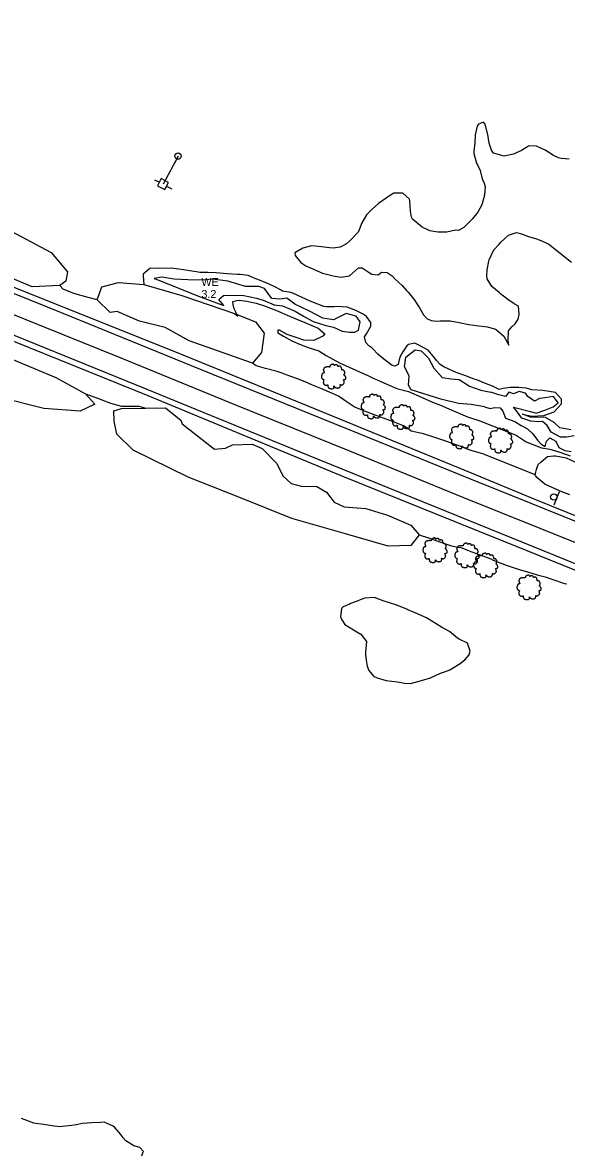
# Model space of a CAD drawing. Extents: x 2160437 to 2172832, y 205694 to 212444.
# Drawn here: x 2166438 to 2166778, y 208658 to 209361 of the extents above; entities that cross this region are included whole.
import ezdxf

# ---------------------------------------------------------------- set-up
doc = ezdxf.new("R2010")
doc.units = 0
for name, color, linetype in [('RD_EX_BldgApp', 7, 'Continuous'), ('RD_EX_H2O_Pond', 7, 'Continuous'), ('RD_EX_H2O_txCode', 7, 'Continuous'), ('RD_EX_LaneStripe', 7, 'Continuous'), ('RD_EX_Road', 7, 'Continuous'), ('RD_EX_UT', 7, 'Continuous'), ('RD_EX_UT_Guy', 7, 'Continuous'), ('RD_EX_VEG', 7, 'Continuous'), ('RD_EX_VEG_ShrubLine', 7, 'Continuous'), ('RD_EX_VEG_TreeLine', 7, 'Continuous')]:
    doc.layers.add(name, color=color, linetype=linetype)

# ---------------------------------------------------------------- blocks, each defined once
blk = doc.blocks.new('T2')
at = {"layer": 'RD_EX_VEG'}
for points in [[(0.05, 7.21), (-0.25, 7.24), (-0.57, 7.14), (-0.82, 7.04), (-1.05, 6.96), (-1.27, 6.86), (-1.57, 6.69), (-1.8, 6.49), (-1.92, 6.24), (-1.97, 6.01), (-2.02, 5.74), (-2.02, 5.56), (-2.15, 5.54), (-2.3, 5.56), (-2.55, 5.64), (-2.8, 5.64), (-3.05, 5.64), (-3.4, 5.61), (-3.75, 5.61), (-4.02, 5.56), (-4.35, 5.51), (-4.72, 5.39), (-5.07, 5.26), (-5.37, 5.01), (-5.62, 4.54), (-5.75, 4.19), (-5.9, 3.94), (-5.75, 3.49), (-5.57, 3.14), (-5.55, 2.94), (-5.47, 2.52), (-5.37, 2.29), (-5.25, 2.09), (-5.32, 2.07), (-5.7, 2.02), (-6, 1.92), (-6.42, 1.69), (-6.64, 1.47), (-6.74, 1.14), (-6.77, 0.79), (-6.87, 0.59), (-6.94, 0.32), (-6.97, 0.24), (-7.02, -0.08), (-6.92, -0.53), (-6.89, -0.88), (-6.77, -1.11), (-6.62, -1.28), (-6.44, -1.53), (-6.05, -1.76), (-5.72, -1.86), (-5.52, -1.88), (-5.7, -2.38), (-5.75, -2.73), (-5.87, -3.13), (-5.87, -3.21), (-5.92, -3.68), (-5.77, -4.01), (-5.7, -4.38), (-5.52, -4.61), (-5.25, -4.91), (-4.92, -5.13), (-4.42, -5.26), (-4.02, -5.23), (-3.45, -5.06), (-3.2, -4.98), (-3.22, -5.16), (-3.2, -5.53), (-3.2, -5.96), (-3.05, -6.28), (-2.95, -6.56), (-2.8, -6.81), (-2.47, -7.03), (-2.07, -7.11), (-1.65, -7.26), (-1.2, -7.33), (-0.7, -7.36), (-0.1, -7.21), (0.18, -7.08), (0.28, -6.91), (0.48, -6.53), (0.43, -6.31), (0.45, -5.71), (0.55, -5.88), (0.73, -6.23), (1.23, -6.53), (1.63, -6.71), (2.1, -6.86), (2.4, -6.93), (2.88, -6.86), (3.25, -6.78), (3.63, -6.66), (3.93, -6.38), (4.1, -6.11), (4.15, -5.83), (4.23, -5.46), (4.28, -5.28)], [(4.28, -5.28), (4.2, -5.11), (4.15, -4.86), (4.23, -4.88), (4.4, -4.93), (4.68, -5.06), (4.9, -5.13), (5.23, -5.11), (5.5, -5.01), (5.95, -4.73), (6.22, -4.26), (6.5, -3.86), (6.57, -3.53), (6.52, -3.31), (6.5, -2.81), (6.3, -2.56), (6.25, -2.43), (6.15, -2.03), (6.22, -1.98), (6.5, -1.93), (6.87, -1.81), (7.15, -1.68), (7.37, -1.51), (7.45, -1.28), (7.42, -0.88), (7.47, -0.48), (7.4, -0.33), (7.3, -0.18), (7.22, 0.02), (7.07, 0.17), (6.97, 0.32), (6.87, 0.42), (6.75, 0.57), (6.57, 0.69), (6.42, 0.74), (6.37, 0.89), (6.52, 1.09), (6.57, 1.19), (6.6, 1.42), (6.82, 1.77), (6.87, 2.17), (6.82, 2.59), (6.77, 2.87), (6.62, 3.14), (6.42, 3.39), (6.3, 3.56), (6.12, 3.69), (5.8, 3.81), (5.55, 3.86), (5.2, 3.86), (5, 3.91), (5.03, 3.96), (5.03, 4.11), (5.03, 4.39), (4.95, 4.84), (4.8, 5.34), (4.8, 5.36), (4.7, 5.61), (4.48, 5.81), (4.3, 5.91), (4.1, 6.04), (3.85, 6.06), (3.55, 6.06), (3.28, 6.01), (3.08, 5.91), (2.9, 5.79), (2.83, 5.94), (2.73, 6.24), (2.68, 6.39), (2.53, 6.56), (2.3, 6.76), (1.85, 6.89), (1.23, 6.81), (0.93, 6.61), (0.78, 6.44), (0.73, 6.56), (0.53, 6.76), (0.43, 6.94), (0.25, 7.06), (0.1, 7.16), (0, 7.21)]]:
    blk.add_spline(points, degree=3, dxfattribs=at)
blk = doc.blocks.new('PP')
at = {"layer": 'RD_EX_UT'}
for p, q in [((2.49, 2.51), (-2.51, 2.51)), ((-2.51, 2.51), (-2.51, -2.49)), ((2.49, -2.49), (2.49, 2.51)), ((-5.94, -0.05), (-2.47, -0.05)), ((-2.51, -2.49), (2.49, -2.49)), ((2.42, -0.05), (6.06, -0.05))]:
    blk.add_line(p, q, dxfattribs=at)

msp = doc.modelspace()

# ---------------------------------------------------------------- linework, layer by layer
at = {"layer": 'RD_EX_BldgApp'}
msp.add_line((2166770.22, 209059.45), (2166773.47, 209067.85), dxfattribs=at)
msp.add_circle((2166769.97, 209064.4), 2, dxfattribs=at)
at = {"layer": 'RD_EX_H2O_Pond'}
msp.add_lwpolyline([(2166647.86, 209168.59), (2166649.04, 209173.76), (2166646.54, 209177.41), (2166640.2, 209178.95), (2166636.96, 209177.34), (2166632.2, 209175.04), (2166625.66, 209176), (2166616.89, 209180.68), (2166608.09, 209184.88), (2166603.19, 209188.53), (2166598.68, 209187.98), (2166593.83, 209188.42), (2166589.09, 209194.58), (2166585.54, 209195.76), (2166577.32, 209195.92), (2166566.35, 209199.18), (2166556.72, 209200.45), (2166552.2, 209200.02), (2166545.52, 209199.73), (2166532.74, 209200.44), (2166524.94, 209201.67), (2166520.32, 209200.75), (2166523.06, 209199.88), (2166547.93, 209189.75), (2166560.8, 209184.98), (2166563.83, 209183.97), (2166560.71, 209187.72), (2166563.56, 209190.16), (2166568.4, 209190.5), (2166576.3, 209190.31), (2166584.19, 209188.62), (2166588.31, 209187.24), (2166595.17, 209184.33), (2166600.44, 209183.76), (2166608.32, 209180.45), (2166613.52, 209177.33), (2166619.51, 209174.09), (2166627.44, 209171.54), (2166632.33, 209170.54), (2166637.81, 209167.89), (2166642.27, 209167.26), (2166645.65, 209167.3)], close=True, dxfattribs=at)
for points in [[(2166726.72, 209120.69), (2166718.4, 209122.1), (2166710.33, 209122.85), (2166699.34, 209125.52), (2166680.77, 209131.24), (2166679.25, 209134.14), (2166679.67, 209140.14), (2166676.75, 209145.78), (2166677.59, 209151.65), (2166683.31, 209156.35), (2166687.16, 209155.69), (2166691.74, 209151.05), (2166694.98, 209144.78), (2166700.16, 209139.08), (2166705.89, 209138.19), (2166710.73, 209137.75), (2166717.23, 209133.62), (2166724.47, 209131.02), (2166730.54, 209129.84)], [(2166782.67, 209102.57), (2166777.82, 209101.78), (2166774.14, 209101.77), (2166768.26, 209104.88), (2166765.88, 209108.95), (2166762.98, 209111.64), (2166760.38, 209111.39), (2166755.6, 209111.69), (2166749.89, 209113.53), (2166746.59, 209118.21), (2166744.83, 209120.5), (2166755.44, 209117.8), (2166758.93, 209116.84), (2166764.27, 209118.59), (2166769.57, 209120.79), (2166772.61, 209123.22), (2166769.69, 209127.09), (2166764.42, 209126.31), (2166761.01, 209125.8), (2166757.92, 209124.22), (2166753.72, 209127.18), (2166752.22, 209129.24), (2166748.4, 209130.28), (2166744.72, 209128.9), (2166741.94, 209129.92), (2166739.71, 209127.19), (2166735.63, 209128.24), (2166730.54, 209129.84)], [(2166726.72, 209120.69), (2166730.19, 209119.68), (2166732.98, 209120.34), (2166736.49, 209120.12), (2166738.12, 209118.07), (2166739.81, 209113.56), (2166745.7, 209111.57), (2166749.5, 209109.1), (2166753.61, 209107.05), (2166756.86, 209103.76), (2166759.71, 209099.91), (2166761.86, 209097.63), (2166764.56, 209096.03), (2166765.4, 209099.26), (2166767.46, 209101.32), (2166771.17, 209099.2), (2166773.04, 209095.36), (2166776.92, 209093.47), (2166780.77, 209092.9)]]:
    msp.add_lwpolyline(points, dxfattribs=at)
at = {"layer": 'RD_EX_LaneStripe'}
msp.add_lwpolyline([(2166025.36, 209344.25), (2166108.97, 209310.08), (2166179, 209281.39), (2166248.32, 209253.24), (2166322.6, 209223.02), (2166428.12, 209180.09), (2166499.44, 209151.2), (2166571.15, 209122.03), (2166642.26, 209093.12), (2166713.47, 209064.17), (2166784.54, 209035.5), (2166854.09, 209007.34), (2166996.21, 208949.61), (2167074.48, 208917.74), (2167146.55, 208888.33)], dxfattribs=at)
at = {"layer": 'RD_EX_Road'}
for points in [[(2166026.17, 209360.72), (2166104.45, 209329.24), (2166218.97, 209282.28), (2166318.19, 209241.85), (2166429.86, 209196.42), (2166532.44, 209155.56), (2166615.15, 209121.73), (2166718.37, 209079.44), (2166758.57, 209062.93), (2166826.99, 209035.09), (2166891.12, 209009.17), (2166956.69, 208982.6), (2167013.45, 208959.75), (2167046.21, 208945.39), (2167108.06, 208919.54), (2167125.82, 208911.38), (2167128.12, 208905.84)], [(2166024.71, 209357.76), (2166117.95, 209319.57), (2166186.21, 209291.8), (2166298.24, 209246.06), (2166371.62, 209216.13), (2166463.14, 209179.26), (2166548.9, 209144.32), (2166648.16, 209104.03), (2166717.23, 209075.95), (2166755.68, 209060.57), (2166838.17, 209027.28), (2166917.84, 208994.71), (2167010.25, 208956.85), (2167067.32, 208932.42), (2167128.12, 208905.84), (2167149.74, 208896.27)], [(2166015.83, 209334.81), (2166072.81, 209311.37), (2166182.98, 209266.77), (2166282.53, 209226.31), (2166401.71, 209177.97), (2166514.59, 209132.05), (2166616.41, 209090.49), (2166709.27, 209052.8), (2166770.4, 209027.97), (2166845.06, 208997.67), (2166946.51, 208956.61), (2167027.58, 208923.96), (2167082.42, 208902.57), (2167142.85, 208879.55)], [(2166014.65, 209331.72), (2166089.07, 209301.24), (2166186.34, 209261.39), (2166293.04, 209218.16), (2166386.32, 209180.32), (2166516.17, 209127.72), (2166639.01, 209076.95), (2166708.04, 209049.04), (2166753.09, 209031.03), (2166819.33, 209004.22), (2166878.6, 208980.23), (2166936.73, 208956.62), (2166973.88, 208941.43), (2167018.87, 208923.18), (2167070.62, 208903.38), (2167105.14, 208890.26), (2167142.48, 208878.61)]]:
    msp.add_lwpolyline(points, dxfattribs=at)
at = {"layer": 'RD_EX_UT'}
msp.add_line((2166535.15, 209277.3), (2166532.84, 209272.87), dxfattribs=at)
msp.add_circle((2166535.15, 209277.3), 2, dxfattribs=at)
at = {"layer": 'RD_EX_UT_Guy'}
msp.add_lwpolyline([(2166535.15, 209277.3), (2166525.77, 209259.79)], dxfattribs=at)
at = {"layer": 'RD_EX_VEG_ShrubLine'}
for points in [[(2166779.52, 209275.39), (2166774.51, 209275.73), (2166772.84, 209276.29), (2166769.72, 209277.76), (2166764.47, 209280.91), (2166764.47, 209280.91), (2166759.24, 209283.44), (2166755.09, 209283.69), (2166754.09, 209283.48), (2166749.78, 209280.85), (2166749.78, 209280.85), (2166744.68, 209278.59), (2166738.87, 209277.3), (2166738.87, 209277.3), (2166732.2, 209279.16), (2166732.2, 209279.16), (2166731.08, 209280.93), (2166729.5, 209285.43), (2166728.84, 209290.77), (2166726.98, 209297.19), (2166726.02, 209298.52), (2166722.81, 209297.27), (2166722.01, 209296.01), (2166720.93, 209290.55), (2166720.6, 209285.29), (2166719.96, 209280.65), (2166719.91, 209278.81), (2166721.67, 209272.97), (2166722.13, 209272.28), (2166723.98, 209268.39), (2166725.25, 209263.19), (2166726.37, 209260.34), (2166727.12, 209258.02), (2166726.7, 209252.8), (2166725.08, 209246.81), (2166725.08, 209246.81), (2166722.52, 209242.19), (2166718.94, 209237.86), (2166718.31, 209237.24), (2166713.71, 209232.64), (2166710.43, 209230.82), (2166708.52, 209231.13), (2166703.19, 209229.81), (2166703.19, 209229.81), (2166697.5, 209229.73), (2166692.47, 209230.56), (2166692.47, 209230.56), (2166687.74, 209232.87), (2166681.65, 209237.89), (2166680.94, 209239.24), (2166680.35, 209242.86), (2166680.03, 209249.5), (2166679.85, 209250.3), (2166675.68, 209254.1), (2166675.13, 209254.23), (2166670.01, 209254.19), (2166667.34, 209252.39), (2166665.14, 209250.98), (2166660.5, 209247.6), (2166656.54, 209244.16), (2166656.54, 209244.16), (2166652.86, 209240.53), (2166650, 209235.51), (2166648.43, 209231.23), (2166647.75, 209229.85), (2166642.37, 209224.17), (2166640.38, 209222.54), (2166636.37, 209220.44), (2166632.15, 209219.76), (2166629.77, 209219.93), (2166624.79, 209220.61), (2166620.9, 209221.04), (2166618.54, 209221.27), (2166613.2, 209219.82), (2166608.05, 209216.8), (2166608.32, 209215.12), (2166611.92, 209210.85), (2166614.97, 209208.81), (2166618.29, 209207.26), (2166625.35, 209204.26), (2166631.99, 209202.59), (2166631.99, 209202.59), (2166637.13, 209201.72), (2166642.26, 209202.59), (2166642.26, 209202.59), (2166647.98, 209207.41), (2166650.2, 209207.54), (2166653.98, 209205), (2166656.3, 209203.48), (2166660.19, 209203.04), (2166662.38, 209204.7), (2166665.89, 209204.62), (2166668.94, 209202.47), (2166670.56, 209200.6), (2166675.31, 209196.47), (2166678.01, 209193.4), (2166679.06, 209192.38), (2166683.1, 209187.08), (2166684.7, 209184.38), (2166685.98, 209182.54), (2166688.58, 209178.06), (2166690.61, 209175.89), (2166693.23, 209174.64), (2166696.66, 209174.24), (2166699, 209174.39), (2166705.13, 209174.39), (2166710.77, 209173.29), (2166710.77, 209173.29), (2166716.97, 209172.12), (2166723.15, 209171.32), (2166723.15, 209171.32), (2166728.43, 209170.63), (2166733.46, 209169.14), (2166734.26, 209168.78), (2166738.71, 209164.91), (2166741.81, 209159.13), (2166741.43, 209161.89), (2166741.67, 209168.15), (2166743.72, 209170.71), (2166745.78, 209172.48), (2166747.77, 209175.55), (2166748.27, 209178.27), (2166747.81, 209183.64), (2166745.3, 209185.01), (2166741.29, 209187.72), (2166736.66, 209191.31), (2166735.74, 209192.2), (2166731.16, 209195.77), (2166731.16, 209195.77), (2166728.34, 209200.58), (2166728.1, 209202.43), (2166728.29, 209206.19), (2166729.39, 209211.7), (2166729.65, 209212.55), (2166732.54, 209218.7), (2166736.03, 209222.59), (2166736.86, 209223.48), (2166741.7, 209227.97), (2166741.7, 209227.97), (2166746.61, 209229.54), (2166749.76, 209228.78), (2166754.14, 209227.17), (2166759.11, 209225.53), (2166762.86, 209224.26), (2166766.89, 209222.27), (2166780.95, 209210.98)], [(2166780.67, 209106.41), (2166773.72, 209107.58), (2166770.22, 209110.97), (2166764.8, 209114), (2166755.42, 209114.33), (2166750.45, 209116.15), (2166756.26, 209114.95), (2166763.73, 209115.35), (2166770.17, 209117.6), (2166774.84, 209122.52), (2166774.8, 209125.59), (2166770.97, 209129.64), (2166763.1, 209130.97), (2166756.18, 209131.24), (2166752.68, 209132.46), (2166748.13, 209132.72), (2166742.77, 209132.72), (2166738.37, 209132.23), (2166735.86, 209131.5), (2166731.67, 209133.53), (2166727.21, 209135.24), (2166727.21, 209135.24), (2166722.38, 209137.29), (2166719.52, 209138.28), (2166714.96, 209140.03), (2166709.02, 209142.05), (2166709.02, 209142.05), (2166704.3, 209144.24), (2166701.19, 209145.75), (2166698.96, 209147.18), (2166696.6, 209149.56), (2166695.54, 209151.07), (2166691.54, 209156.05), (2166691.54, 209156.05), (2166685.7, 209159.22), (2166683.1, 209160.39), (2166679.25, 209159.72), (2166678.19, 209158.82), (2166675.64, 209155.04), (2166673.94, 209152.2), (2166673.35, 209149.95), (2166672.68, 209147.13), (2166670.61, 209146.01), (2166668.88, 209146.55), (2166665.44, 209149.19), (2166664.88, 209149.68), (2166659.98, 209153.62), (2166656.96, 209156.91), (2166656.35, 209157.55), (2166654.43, 209158.77), (2166652.46, 209160.8), (2166651.73, 209164.37), (2166653, 209166.26), (2166655.65, 209171.07), (2166655.68, 209173.41), (2166652.86, 209177.14), (2166650.38, 209178.85), (2166646.21, 209180.92), (2166640.83, 209182.86), (2166640.83, 209182.86), (2166634.61, 209183.31), (2166632.73, 209183.14), (2166627.83, 209183.06), (2166626.35, 209183.37), (2166622.57, 209184.72), (2166617.73, 209186.65), (2166617.73, 209186.65), (2166612.68, 209189.05), (2166606.91, 209191.71), (2166605.67, 209192.15), (2166600.37, 209192.91), (2166599.09, 209193.67), (2166596, 209195.48), (2166591.65, 209197.44), (2166589.21, 209198.54), (2166584.3, 209200.45), (2166583.7, 209200.72), (2166578.96, 209202.74), (2166574.21, 209203.25), (2166572.37, 209203.3), (2166565.78, 209203.75), (2166558.96, 209204.35), (2166558.96, 209204.35), (2166553.85, 209204.61), (2166548.83, 209204.65), (2166546.68, 209205.08), (2166543.79, 209205.48), (2166538.46, 209206.32), (2166530.97, 209207.29), (2166523.4, 209207.16), (2166518.66, 209207.31), (2166517.57, 209207.14), (2166513.37, 209203.56), (2166513.39, 209202.53), (2166513.73, 209197.03)], [(2166484.61, 209187.45), (2166478.88, 209189), (2166470.1, 209191.52), (2166463.42, 209194.28), (2166461.18, 209196.38)], [(2166570.45, 209179.05), (2166572.46, 209177.37), (2166570.29, 209181.89), (2166569.55, 209184.51), (2166569.45, 209186.42), (2166571.99, 209187.13), (2166573.65, 209187.34), (2166578.14, 209186.77), (2166583.97, 209185.46), (2166583.97, 209185.46), (2166589.21, 209183.76), (2166596.59, 209180.92), (2166599.51, 209179.66), (2166603.32, 209178), (2166608.86, 209175.75), (2166614.45, 209173.35), (2166618.79, 209171.52), (2166622.8, 209169.89), (2166626.79, 209166.35), (2166625.6, 209164.91), (2166619.93, 209162.05), (2166619.93, 209162.05), (2166613.71, 209162.39), (2166608.87, 209164.03), (2166608.87, 209164.03), (2166603.35, 209165.8), (2166598.46, 209168.66), (2166597.5, 209168.55), (2166597.59, 209167.01), (2166601.04, 209164.8), (2166606.28, 209161.89), (2166611.07, 209159.74), (2166611.07, 209159.74), (2166616.4, 209157.7), (2166623.03, 209155.73), (2166627.66, 209152.68), (2166635.98, 209148.22), (2166646.2, 209143.55), (2166654.09, 209140), (2166657.48, 209138.47), (2166659.5, 209137.62), (2166665.55, 209134.78), (2166671.89, 209132.16), (2166679.19, 209130.25), (2166687.68, 209126.55), (2166694.19, 209123.68), (2166699.06, 209121.67), (2166704.27, 209119.38), (2166716.09, 209114.41), (2166723.72, 209111.88), (2166746.49, 209103.06), (2166752.64, 209098.89), (2166762.36, 209095.04), (2166767.44, 209094.17), (2166773.83, 209092.32), (2166780.16, 209090.2)], [(2166725.52, 209091.27), (2166717.5, 209093.74), (2166711.8, 209095.89), (2166702.49, 209099.36), (2166696.26, 209101.26), (2166688.56, 209103.77), (2166680.79, 209105.47), (2166679.16, 209107.04), (2166675.98, 209108.78), (2166667.53, 209112.16), (2166657.23, 209115.96), (2166650.63, 209118.51), (2166645.27, 209120.63), (2166640.26, 209124.03), (2166636.04, 209126.95), (2166635.35, 209127.26), (2166629.82, 209129.81), (2166624.31, 209132.23), (2166622.21, 209133.05), (2166619.15, 209134.25), (2166614.51, 209136.23), (2166609.8, 209138.17), (2166609.11, 209138.36), (2166603.31, 209140.55), (2166600.24, 209141.75), (2166597.06, 209142.7), (2166589.88, 209144.62), (2166583.98, 209146.31), (2166581.76, 209148.01)], [(2166477.28, 209128.87), (2166485.44, 209125.8), (2166493.01, 209122.99), (2166499.77, 209121.2), (2166504.78, 209121.11), (2166510.69, 209121.03), (2166515.12, 209119.88)], [(2166758.29, 209078.17), (2166725.52, 209091.27)], [(2166685.87, 209040.77), (2166691.68, 209038.88), (2166697.43, 209036.71), (2166705.36, 209034.16), (2166709.84, 209033.16), (2166711.89, 209032.78), (2166718.66, 209030.21), (2166725.7, 209027.7), (2166730.56, 209025.69), (2166732.16, 209024.85), (2166740.2, 209021.82), (2166746.47, 209019.72), (2166751.19, 209018.32), (2166753.48, 209017.59), (2166759.57, 209015.76), (2166764.52, 209014.45), (2166769.3, 209012.78), (2166776.7, 209010.41), (2166778.04, 209010.06)], [(2166514.47, 208644.61), (2166511.63, 208650.58), (2166513.45, 208655.41), (2166513.54, 208655.61), (2166511.28, 208658.07), (2166507.56, 208659.14), (2166502.48, 208662.27), (2166500.93, 208664.17), (2166499.33, 208666.22), (2166495.37, 208670.76), (2166494.6, 208671.47), (2166489.01, 208673.99), (2166486.66, 208673.84), (2166481.23, 208673.52), (2166475.41, 208673.14), (2166471.42, 208672.29), (2166468.7, 208671.84), (2166462.69, 208671.3), (2166461.76, 208671.12), (2166457.63, 208671.54), (2166450.97, 208672.5), (2166445, 208673.38), (2166445, 208673.38), (2166437.28, 208676.26)]]:
    msp.add_lwpolyline(points, dxfattribs=at)
msp.add_lwpolyline([(2166704.84, 208980.32), (2166699.87, 208983.16), (2166690.32, 208988.9), (2166683.42, 208992.13), (2166678.72, 208993.95), (2166678.07, 208994.24), (2166671.21, 208997.03), (2166663.24, 208999.6), (2166657.89, 209001.59), (2166657.89, 209001.59), (2166651.85, 209001.13), (2166649.05, 209000.1), (2166647, 208999.29), (2166642.84, 208997.79), (2166642.24, 208997.52), (2166638.24, 208995.72), (2166637.35, 208994.8), (2166636.58, 208989.62), (2166637.42, 208987.62), (2166639.35, 208984.71), (2166644.75, 208981.37), (2166646.79, 208980.28), (2166649.45, 208978.72), (2166652.99, 208974.06), (2166652.99, 208974.06), (2166652.25, 208967.48), (2166652.31, 208966.13), (2166652.77, 208962.5), (2166653.42, 208958.73), (2166654.46, 208955.97), (2166657.3, 208952.53), (2166659.6, 208951.38), (2166665.18, 208949.76), (2166665.18, 208949.76), (2166672.37, 208949.05), (2166676.65, 208948.14), (2166680.48, 208947.98), (2166687.32, 208949.82), (2166692.94, 208951.5), (2166692.94, 208951.5), (2166699.25, 208954.3), (2166702.24, 208955.48), (2166705.05, 208956.38), (2166710.33, 208959.7), (2166710.81, 208959.97), (2166714.41, 208962.61), (2166717.02, 208965.76), (2166717.77, 208968.07), (2166715.97, 208973.15), (2166715.97, 208973.15), (2166710.77, 208975.61), (2166709.71, 208976.2)], close=True, dxfattribs=at)
at = {"layer": 'RD_EX_VEG_TreeLine'}
for points in [[(2166328.42, 209254.25), (2166325.68, 209263.78), (2166330.57, 209267.7), (2166348.33, 209262.46), (2166387.68, 209249.66), (2166430.38, 209230.55), (2166455.81, 209217), (2166466.1, 209204.91), (2166465.06, 209199.13), (2166461.18, 209196.38), (2166444.01, 209195.55), (2166367.34, 209227.89), (2166345.43, 209244.07)], [(2166583.56, 209173.75), (2166589.07, 209166.64), (2166587.38, 209154.61), (2166581.76, 209148.01), (2166542.03, 209161.82), (2166527.1, 209170.17), (2166511.03, 209174.1), (2166497.03, 209180.23), (2166492.81, 209179.66), (2166484.61, 209187.45), (2166487.44, 209195.6), (2166497.9, 209198.28), (2166513.73, 209197.03), (2166537.59, 209190.25), (2166570.45, 209179.05)], [(2166495.2, 209111.85), (2166495.04, 209118.29), (2166499.77, 209119.58), (2166515.12, 209119.88), (2166527.24, 209120.12), (2166536.9, 209112.35), (2166537.82, 209110.13), (2166550.13, 209100.26), (2166557.95, 209094.28), (2166564.82, 209094.85), (2166569.08, 209097.04), (2166581.4, 209097.32), (2166587.66, 209094.68), (2166596.96, 209085.21), (2166600.66, 209077.53), (2166605.9, 209072.89), (2166612.07, 209071.25), (2166621.86, 209070.86), (2166627.89, 209067.31), (2166632.63, 209061.15), (2166639.02, 209058.15), (2166652.55, 209057.22), (2166666.08, 209053.11), (2166680.58, 209046.76), (2166685.87, 209040.77), (2166680.72, 209034.14), (2166666.44, 209033.78), (2166639.7, 209041.38), (2166606.36, 209050.99), (2166573.19, 209064.31), (2166541.43, 209076.76), (2166507.19, 209093.56), (2166496.85, 209103.56)]]:
    msp.add_lwpolyline(points, close=True, dxfattribs=at)
for points in [[(2166416.63, 209156.43), (2166458.8, 209138.94), (2166477.28, 209128.87), (2166483.13, 209122.27), (2166474.04, 209118.08), (2166451.29, 209119.61), (2166424.84, 209126.36)], [(2166779.9, 209065.8), (2166775.03, 209067.7), (2166773.59, 209068.23), (2166764.43, 209072.33), (2166759.44, 209076.59), (2166758.29, 209078.17), (2166759.1, 209081.6), (2166760.26, 209084.7), (2166761.98, 209086.28), (2166766.12, 209089.64), (2166769.7, 209090.13), (2166771.02, 209090.15), (2166777.6, 209088.84), (2166783.07, 209086.36)]]:
    msp.add_lwpolyline(points, dxfattribs=at)

# ---------------------------------------------------------------- block references
at = {"layer": 'RD_EX_UT', "xscale": 1.02, "yscale": 1.02, "rotation": -27.504492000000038}
msp.add_blockref('PP', (2166525.77, 209259.79), dxfattribs=at)
at = {"layer": 'RD_EX_VEG', "xscale": 1.0499999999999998, "yscale": 1.0499999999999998}
for p in [(2166632.13, 209139.71), (2166656.86, 209121), (2166675.39, 209114.4), (2166712.16, 209102.28), (2166736.46, 209099.69), (2166695.51, 209031.22), (2166715.45, 209028), (2166727.17, 209021.76), (2166754.26, 209008)]:
    msp.add_blockref('T2', p, dxfattribs=at)

# ---------------------------------------------------------------- texts
at = {"layer": 'RD_EX_H2O_txCode'}
for s, p in [('WE', (2166549.78, 209196.17)), ('3.2', (2166549.78, 209188.67))]:
    msp.add_text(s, height=5, dxfattribs=at).set_placement(p)

doc.saveas('drawing.dxf')
